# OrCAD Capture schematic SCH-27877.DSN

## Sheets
1 TITLE PAGE: title: TWRPI-PROXIMITY; rev: B; company: Freescale Semiconductor; note: SCH-27877 PDF: SPF-27877; note: 6501 William Cannon Drive West; note: Austin, TX 78735-8598
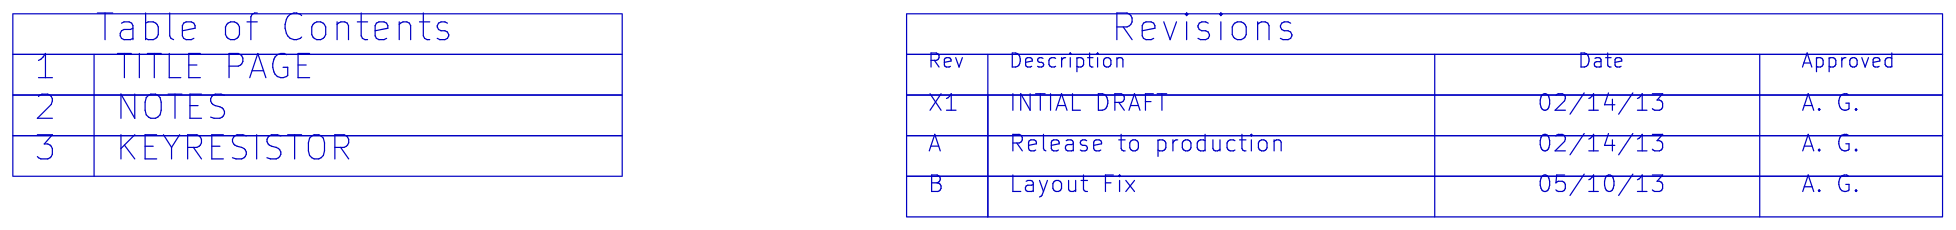
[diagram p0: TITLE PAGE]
2 NOTES
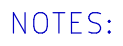
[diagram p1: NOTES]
3 KEYRESISTOR: size A; note: Roznov p.R. 756 61, CZ
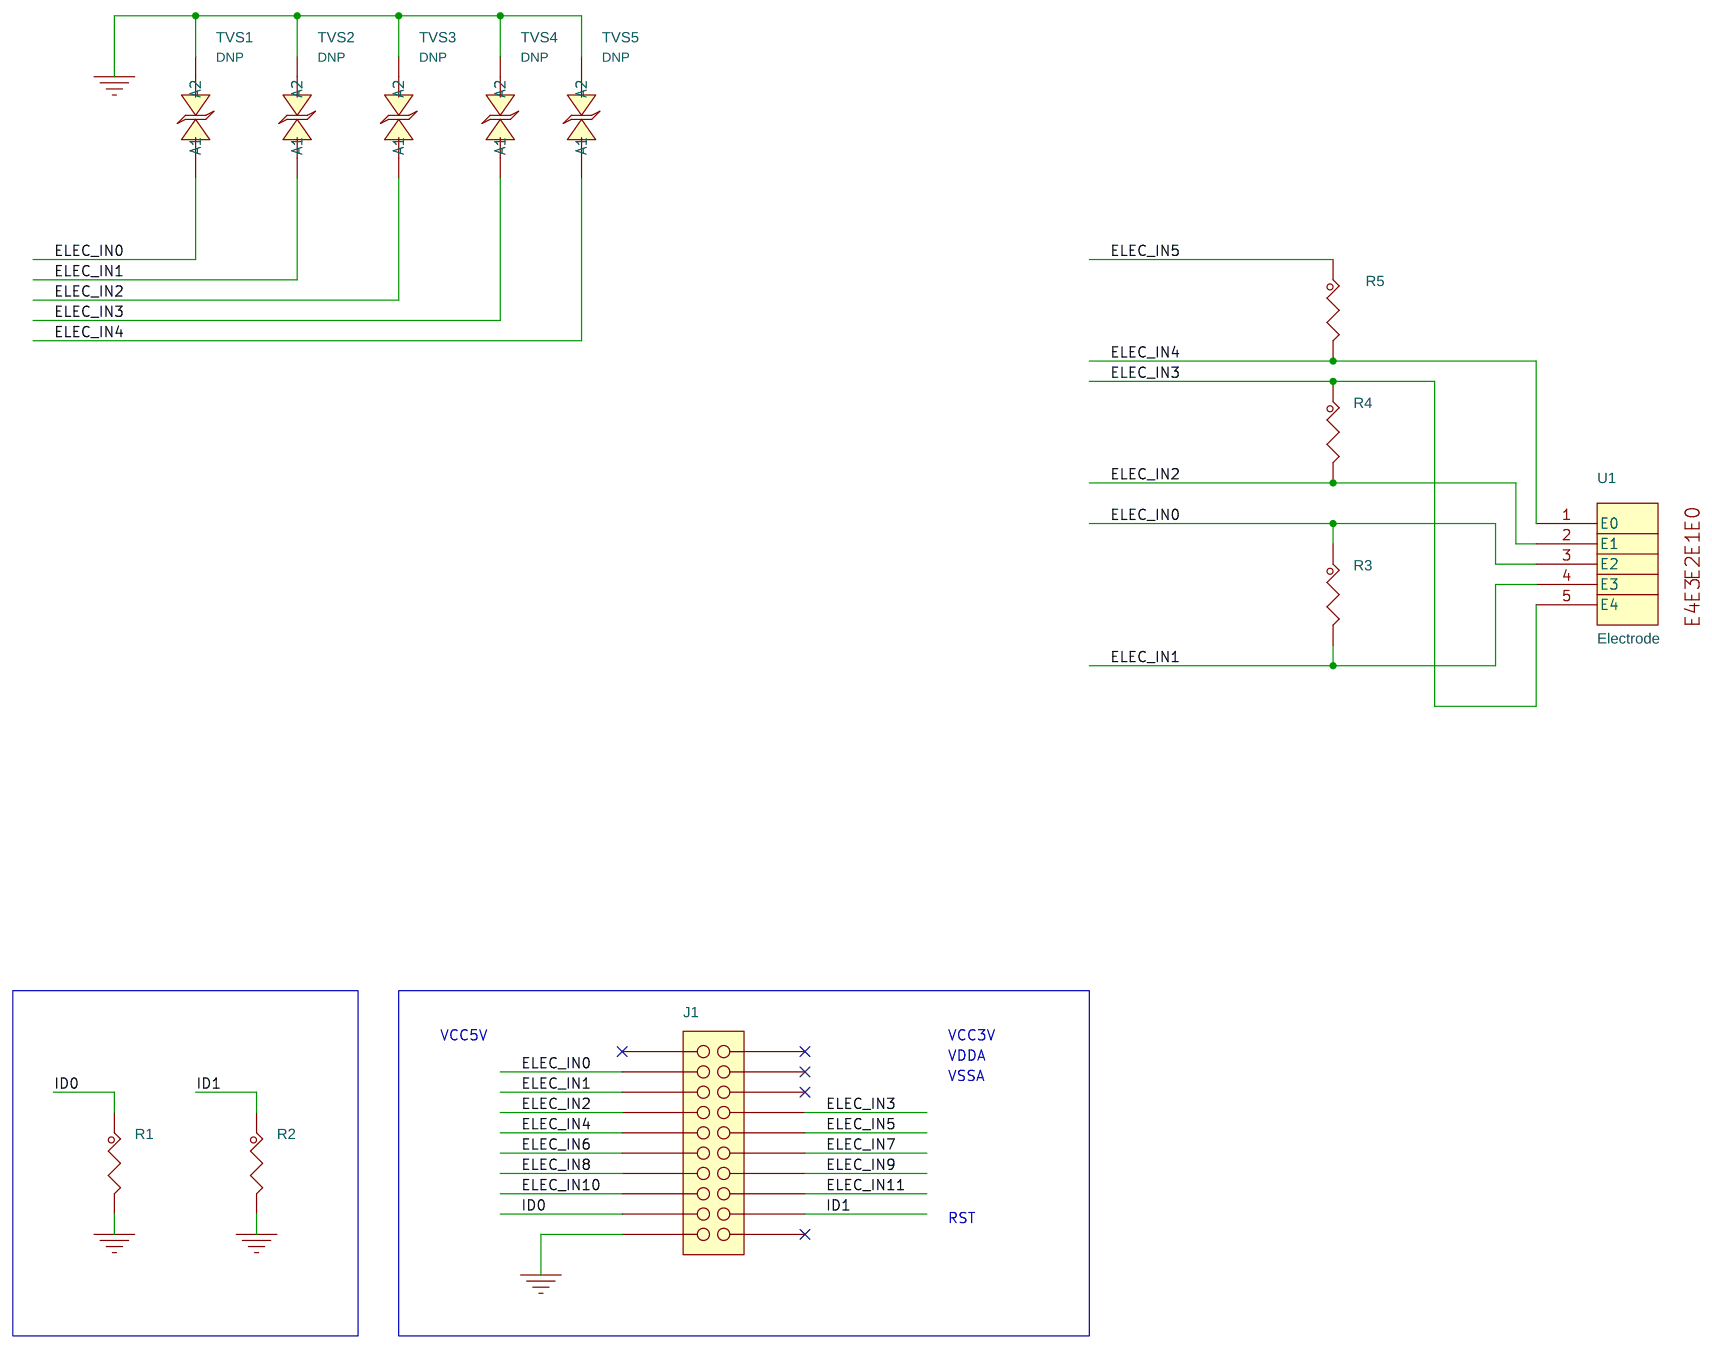
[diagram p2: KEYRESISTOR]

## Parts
J1  SFC-110-T2-L-D-A  [con_sfc_20f_50_sm]
R1  18K  [RC0603_OV]
R2  0  [RC0603_OV]
R3  1.0M  [RC0603_OV]
R4  1.0M  [RC0603_OV]
R5  1.0M  [RC0603_OV]
TVS1  PGB2010402KRHF  [diode_0402]
TVS2  PGB2010402KRHF  [diode_0402]
TVS3  PGB2010402KRHF  [diode_0402]
TVS4  PGB2010402KRHF  [diode_0402]
TVS5  PGB2010402KRHF  [diode_0402]
U1  Electrode  [electrode_5p_44x48]

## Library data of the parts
J1 = CONN_HDR_10X2: CON 2X10 SKT SMT 50MIL SP 187H AU; AGILE_PN: 211-78838; CAD_APPROVED: Yes; HEIGHT: 4.75MM; MFG_NAME01: SAMTEC; MFG_PN01: SFC-110-T2-L-D-A-K; ROHS: Yes
R1 = RES: RES MF 18.0K 1/10W 1% 0603; AGILE_PN: 470-30161; CAD_APPROVED: Yes; FPLIST: RC0603_OV,RC0603,0603_CC; MFG_NAME01: KOA SPEER; MFG_PN01: RK73H1JTTD1802F; ROHS: Yes; Tolerance: 1%
R2 = RES: RES MF ZERO OHM 1/10W 1% 0603; AGILE_PN: 470-80217; CAD_APPROVED: Yes; FPLIST: RC0603_OV,RC0603,R603-X2,0603_CC; MFG_NAME01: MULTICOMP; MFG_PN01: MC0603SAF0000T5E; ROHS: Yes; Tolerance: 1%
R3-R5 = RES: RES MF 1.0M 1/10W 1% 0603; AGILE_PN: 470-76249; CAD_APPROVED: Yes; FPLIST: RC0603_OV,RC0603,0603_CC; MFG_NAME01: KOA SPEER; MFG_PN01: RK73H1JTTD1004F; ROHS: Yes; Tolerance: 1%
TVS1-TVS5 = DIODE_TVS_BIDIR: DIODE ESD SUPPRESSOR BIDIR -- 12V 0402; AGILE_PN: 480-78091; ASSY_OPT: DNP; CAD_APPROVED: Yes; HEIGHT: 0.38MM; MFG_NAME01: LITTELFUSE; ROHS: Yes
U1 = ELECTRODE5: CAPACITIVE SHIELDED FIVE ELECTRODE (Not a Part to Order); AGILE_PN: TMP-WF-18731; CAD_APPROVED: Yes; HEIGHT: 0.127MM; MFG_NAME01: NA; PRE_APN: 510-77889; ROHS: Yes

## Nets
GND: J1.19 R1.2 R2.2 TVS1.2(A2) TVS2.2(A2) TVS3.2(A2) TVS4.2(A2) TVS5.2(A2)
ELEC_IN0: J1.3 R3.1 TVS1.1(A1) U1.3(E2)
ELEC_IN1: J1.5 R3.2 TVS2.1(A1) U1.4(E3)
ELEC_IN2: J1.7 R4.2 TVS3.1(A1) U1.2(E1)
ELEC_IN3: J1.8 R4.1 TVS4.1(A1) U1.5(E4)
ELEC_IN4: J1.9 R5.2 TVS5.1(A1) U1.1(E0)
ELEC_IN5: J1.10 R5.1
ELEC_IN6: J1.11
ELEC_IN7: J1.12
ELEC_IN8: J1.13
ELEC_IN9: J1.14
ELEC_IN10: J1.15
ELEC_IN11: J1.16
ID0: J1.17 R1.1
ID1: J1.18 R2.1

Not connected (* = marked no-connect by the designer): J1 1* 2* 4* 6* 20*

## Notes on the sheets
sheet 1
- Table of Contents
- Revisions
- 1
- TITLE PAGE
- Rev
- Description
- Date
- Approved
- 2
- NOTES
- X1
- INTIAL DRAFT
- 02/14/13
- A. G.
- 3
- KEYRESISTOR
- A
- Release to production
- 02/14/13
- A. G.
- B
- Layout Fix
- 05/10/13
- A. G.
sheet 2
- NOTES:
sheet 3
- VCC5V
- VCC3V
- VDDA
- VSSA
- RST
